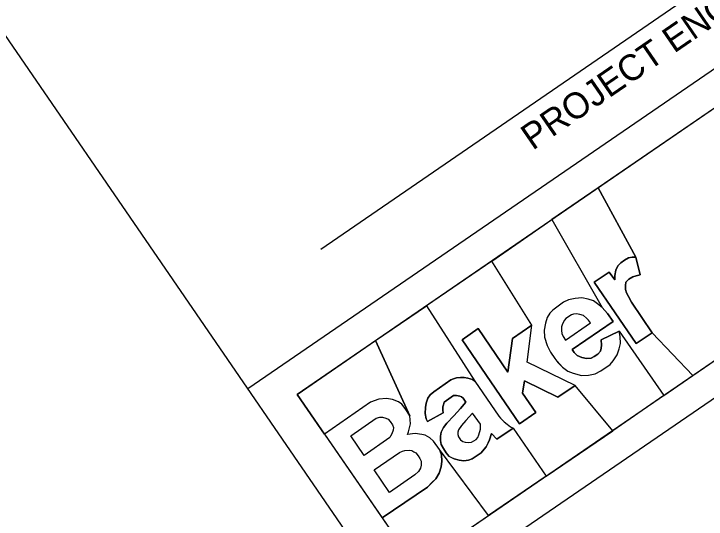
# Model space of a CAD drawing. Extents: x 2385901 to 2398444, y 552503 to 560579.
# Drawn here: x 2397033.1 to 2397262.8, y 560053.3 to 560221 of the extents above; entities that cross this region are included whole.
import ezdxf

# ---------------------------------------------------------------- set-up
doc = ezdxf.new("R2010")
doc.units = 0
doc.layers.add('Old_Level_8', color=7, linetype='Continuous')
doc.layers.add('Prop EOT', color=7, linetype='Continuous')

msp = doc.modelspace()

# ---------------------------------------------------------------- linework, layer by layer
at = {"layer": 'Old_Level_8'}
for p, q in [((2397154.02, 560033.5), (2396965.64, 560308.1)), ((2397407.68, 560300.28), (2397110.74, 560096.58)), ((2397172.79, 560030), (2397447.42, 560218.4)), ((2397230.65, 560135.28), (2397225.6, 560131.91)), ((2397232.47, 560132.66), (2397230.65, 560135.28)), ((2397225.6, 560131.91), (2397239.58, 560111.58)), ((2397244.91, 560115.17), (2397237.99, 560125.3)), ((2397205, 560117.69), (2397198.52, 560113.21)), ((2397187.11, 560116.56), (2397181.8, 560112.77)), ((2397197, 560102.1), (2397187.11, 560116.56)), ((2397239.58, 560111.58), (2397244.91, 560115.17)), ((2397181.8, 560112.77), (2397200.87, 560084.97)), ((2397198.52, 560113.21), (2397197, 560102.1)), ((2397213.54, 560093.74), (2397219.33, 560097.69)), ((2397206.24, 560088.65), (2397201.82, 560095.13)), ((2397151.46, 560092.08), (2397136.21, 560081.53)), ((2397154.25, 560093.12), (2397151.46, 560092.08)), ((2397156.75, 560093.37), (2397154.25, 560093.12)), ((2397158.73, 560092.99), (2397156.75, 560093.37)), ((2397160.67, 560092.2), (2397158.73, 560092.99)), ((2397161.85, 560091.41), (2397160.67, 560092.2)), ((2397164.45, 560087.54), (2397163.42, 560089.37)), ((2397164.71, 560084.87), (2397164.45, 560087.54)), ((2397200.87, 560084.97), (2397206.24, 560088.65)), ((2397144.94, 560080.97), (2397153.28, 560086.84)), ((2397164.03, 560082.25), (2397164.71, 560084.87)), ((2397136.21, 560081.53), (2397155.25, 560053.73)), ((2397144.92, 560080.96), (2397144.94, 560080.97)), ((2397149.3, 560074.44), (2397144.92, 560080.96)), ((2397157.82, 560080.35), (2397149.3, 560074.44)), ((2397163.69, 560081.34), (2397164.03, 560082.25)), ((2397166.21, 560081.7), (2397163.69, 560081.34)), ((2397168.51, 560081.4), (2397166.21, 560081.7)), ((2397169.54, 560081.17), (2397168.51, 560081.4)), ((2397171.15, 560080.23), (2397169.54, 560081.17)), ((2397172.38, 560079.19), (2397171.15, 560080.23)), ((2397174.31, 560076.43), (2397172.38, 560079.19)), ((2397175, 560074.61), (2397174.31, 560076.43)), ((2397152.62, 560069.65), (2397161.05, 560075.43)), ((2397175.07, 560072.56), (2397175, 560074.61)), ((2397174.86, 560070.62), (2397175.07, 560072.56)), ((2397157.71, 560062.14), (2397152.62, 560069.65)), ((2397174.19, 560068.58), (2397174.86, 560070.62)), ((2397166.14, 560068.01), (2397157.71, 560062.14)), ((2397171.81, 560065.47), (2397173.11, 560066.68)), ((2397173.11, 560066.68), (2397174.19, 560068.58)), ((2397170.3, 560063.94), (2397171.81, 560065.47)), ((2397155.25, 560053.73), (2397170.3, 560063.94))]:
    msp.add_line(p, q, dxfattribs=at)
for points in [[(2397275.68, 560196.62), (2397127.13, 560094.71), (2397166.2, 560037.75), (2397314.74, 560139.68)], [(2397227, 560163.25), (2397239.39, 560140.23), (2397240.84, 560134.42), (2397239.5, 560134.08), (2397238.44, 560133.76), (2397237.14, 560132.9), (2397236.15, 560131.93), (2397235.97, 560130.87), (2397235.98, 560129.54), (2397236.35, 560128.45), (2397236.97, 560127.16), (2397237.99, 560125.3), (2397244.91, 560115.17), (2397258.35, 560100.97), (2397314.74, 560139.68), (2397275.68, 560196.62)], [(2397211.62, 560152.7), (2397228.29, 560123.57), (2397230.08, 560121.56), (2397231.93, 560118.9), (2397218.3, 560109.58), (2397219.01, 560108.55), (2397219.97, 560107.58), (2397221.55, 560106.92), (2397223.13, 560106.61), (2397224.6, 560106.68), (2397225.65, 560107.23), (2397226.87, 560108.04), (2397227.72, 560109), (2397227.97, 560109.99), (2397228.1, 560111.04), (2397227.99, 560112.85), (2397233.86, 560115.71), (2397248.69, 560094.31), (2397258.35, 560100.97), (2397244.91, 560115.17), (2397239.58, 560111.58), (2397225.6, 560131.91), (2397230.65, 560135.28), (2397232.47, 560132.66), (2397232.49, 560134.13), (2397232.78, 560135.87), (2397233.44, 560137.4), (2397234.5, 560138.36), (2397235.68, 560139.23), (2397237, 560140.02), (2397238.18, 560140.22), (2397239.39, 560140.23), (2397227, 560163.25)], [(2397233.86, 560115.71), (2397248.69, 560094.31), (2397231.77, 560082.65), (2397219.33, 560097.69), (2397203.39, 560105.35), (2397205, 560117.69), (2397191.63, 560138.96), (2397211.62, 560152.7), (2397228.29, 560123.57), (2397226.73, 560124.74), (2397225.35, 560125.74), (2397223.65, 560126.26), (2397221.58, 560126.73), (2397219.32, 560126.55), (2397217.08, 560126.12), (2397215.44, 560125.29), (2397211.86, 560122.62), (2397210.87, 560121.6), (2397209.99, 560120.21), (2397209.53, 560118.38), (2397209.08, 560115.98), (2397209.2, 560113.73), (2397209.99, 560110.92), (2397211.12, 560108.76), (2397212.52, 560106.64), (2397215.08, 560103.71), (2397216.9, 560102.42), (2397218.65, 560101.7), (2397221.38, 560100.98), (2397223.78, 560101.09), (2397225.96, 560101.56), (2397227.87, 560102.55), (2397230.95, 560104.64), (2397231.9, 560105.87), (2397233.28, 560107.86), (2397233.92, 560109.76), (2397234.32, 560111.55), (2397234.25, 560113.86)], [(2397170, 560124.12), (2397186.07, 560099.12), (2397194.01, 560087.5), (2397194.6, 560086.81), (2397195.78, 560085.6), (2397196.73, 560084.81), (2397197.91, 560083.98), (2397198.74, 560083.5), (2397209.68, 560067.55), (2397231.77, 560082.65), (2397219.33, 560097.69), (2397213.54, 560093.74), (2397202.51, 560099.21), (2397201.82, 560095.13), (2397206.24, 560088.65), (2397200.87, 560084.97), (2397181.8, 560112.77), (2397187.11, 560116.56), (2397197, 560102.1), (2397198.52, 560113.21), (2397205, 560117.69), (2397191.63, 560138.96)], [(2397164.45, 560087.54), (2397153.12, 560112.54), (2397170, 560124.12), (2397186.07, 560099.12), (2397185.21, 560099.66), (2397183.7, 560100.11), (2397182.48, 560100.32), (2397181.32, 560100.31), (2397179.94, 560100.21), (2397178.93, 560099.89), (2397178.08, 560099.57), (2397172.41, 560095.53), (2397171.27, 560094.52), (2397170.48, 560093.46), (2397169.89, 560091.74), (2397169.64, 560090.32), (2397169.55, 560088.37), (2397169.86, 560086.6), (2397170.3, 560085.67), (2397175.56, 560088.52), (2397175.38, 560089.45), (2397175.43, 560090.62), (2397175.6, 560091.26), (2397175.87, 560092.14), (2397179, 560094.32), (2397179.97, 560094.35), (2397181.06, 560094.16), (2397181.58, 560093.91), (2397182.21, 560093.41), (2397183.08, 560092.11), (2397181.23, 560089.97), (2397179.02, 560087.59), (2397176.78, 560085.17), (2397175.67, 560083.74), (2397174.88, 560082.13), (2397174.62, 560080.81), (2397174.67, 560079.42), (2397174.86, 560078.09), (2397175.6, 560076.71), (2397176.5, 560075.35), (2397177.47, 560074.15), (2397179.14, 560073.29), (2397180.84, 560072.85), (2397182.4, 560072.7), (2397183.93, 560072.88), (2397185.1, 560073.33), (2397188.13, 560075.32), (2397188.63, 560075.84), (2397189.75, 560077.34), (2397190.45, 560078.66), (2397190.91, 560079.64), (2397191.56, 560081.69), (2397193.33, 560079.85), (2397198.74, 560083.5), (2397209.68, 560067.55), (2397190.62, 560054.47), (2397174.31, 560076.43), (2397172.38, 560079.19), (2397171.15, 560080.23), (2397169.54, 560081.17), (2397168.51, 560081.4), (2397166.21, 560081.7), (2397163.69, 560081.34), (2397164.03, 560082.25), (2397164.71, 560084.87)], [(2397216.08, 560112.69), (2397224.4, 560118.42), (2397223.74, 560119.31), (2397223.13, 560119.94), (2397222.11, 560120.87), (2397220.89, 560121.25), (2397219.72, 560121.38), (2397218.75, 560121.27), (2397218.06, 560121.09), (2397216.26, 560119.85), (2397215.75, 560119.36), (2397215.13, 560118.06), (2397214.79, 560117.12), (2397214.84, 560115.91), (2397214.95, 560114.85), (2397215.37, 560113.94)], [(2397164.45, 560087.54), (2397163.42, 560089.37), (2397162.58, 560090.42), (2397161.85, 560091.41), (2397160.67, 560092.2), (2397158.73, 560092.99), (2397156.75, 560093.37), (2397154.25, 560093.12), (2397151.46, 560092.08), (2397136.21, 560081.53), (2397127.13, 560094.71), (2397153.12, 560112.54)], [(2397144.94, 560080.97), (2397153.28, 560086.84), (2397154.5, 560087.15), (2397155.46, 560087.14), (2397156.53, 560086.82), (2397157.26, 560086.51), (2397157.97, 560085.66), (2397158.78, 560084.55), (2397159.04, 560083.71), (2397158.9, 560082.81), (2397158.55, 560081.63), (2397158.08, 560080.78), (2397157.82, 560080.35), (2397149.3, 560074.44)], [(2397185.3, 560088.49), (2397183.02, 560086.08), (2397181.66, 560084.42), (2397180.58, 560082.98), (2397180.41, 560082.17), (2397180.36, 560081.43), (2397180.67, 560080.56), (2397181.32, 560079.61), (2397182.11, 560079.05), (2397182.84, 560078.8), (2397183.91, 560078.72), (2397184.94, 560078.84), (2397186.46, 560079.76), (2397187.01, 560080.44), (2397187.33, 560081.29), (2397187.92, 560083.1), (2397187.96, 560084.14), (2397187.89, 560084.85)], [(2397152.62, 560069.65), (2397161.05, 560075.43), (2397162.05, 560075.88), (2397162.86, 560076.06), (2397164.3, 560076.17), (2397165.18, 560076.03), (2397165.82, 560075.65), (2397166.43, 560075.28), (2397167.24, 560074.35), (2397167.78, 560073.38), (2397168.21, 560072.54), (2397168.2, 560071.25), (2397167.98, 560070.17), (2397167.35, 560069.1), (2397166.14, 560068.01), (2397157.71, 560062.14)], [(2397174.31, 560076.43), (2397175, 560074.61), (2397175.07, 560072.56), (2397174.86, 560070.62), (2397174.19, 560068.58), (2397173.11, 560066.68), (2397170.3, 560063.94), (2397155.25, 560053.73), (2397166.2, 560037.75), (2397190.62, 560054.47)]]:
    msp.add_lwpolyline(points, close=True, dxfattribs=at)
for points in [[(2397237.99, 560125.3), (2397236.97, 560127.16), (2397236.35, 560128.45), (2397235.98, 560129.54), (2397235.97, 560130.87), (2397236.15, 560131.93), (2397237.14, 560132.9), (2397238.44, 560133.76), (2397239.5, 560134.08), (2397240.84, 560134.42), (2397239.39, 560140.23), (2397238.18, 560140.22), (2397237, 560140.02), (2397235.68, 560139.23), (2397234.5, 560138.36), (2397233.44, 560137.4), (2397232.78, 560135.87), (2397232.49, 560134.13), (2397232.47, 560132.66)], [(2397218.3, 560109.58), (2397231.93, 560118.9), (2397230.08, 560121.56), (2397228.29, 560123.57), (2397226.73, 560124.74), (2397225.35, 560125.74), (2397223.65, 560126.26), (2397221.58, 560126.73), (2397219.32, 560126.55), (2397217.08, 560126.12), (2397215.44, 560125.29), (2397211.86, 560122.62), (2397210.87, 560121.6), (2397209.99, 560120.21), (2397209.53, 560118.38), (2397209.08, 560115.98), (2397209.2, 560113.73), (2397209.99, 560110.92), (2397211.12, 560108.76), (2397212.52, 560106.64), (2397213.59, 560105.25), (2397215.08, 560103.71), (2397216.9, 560102.42), (2397218.65, 560101.7), (2397221.38, 560100.98), (2397223.78, 560101.09), (2397225.96, 560101.56), (2397227.87, 560102.55), (2397230.95, 560104.64), (2397231.9, 560105.87), (2397233.28, 560107.86), (2397233.92, 560109.76), (2397234.32, 560111.55), (2397234.25, 560113.86), (2397233.86, 560115.71), (2397227.99, 560112.85), (2397228.1, 560111.04), (2397227.97, 560109.99), (2397227.72, 560109), (2397226.87, 560108.04), (2397225.65, 560107.23), (2397224.6, 560106.68), (2397223.13, 560106.61), (2397221.55, 560106.92), (2397219.97, 560107.58), (2397219.01, 560108.55), (2397218.3, 560109.58)], [(2397216.08, 560112.69), (2397224.4, 560118.42), (2397223.74, 560119.31), (2397223.13, 560119.94), (2397222.11, 560120.87), (2397220.89, 560121.25), (2397219.72, 560121.38), (2397218.75, 560121.27), (2397218.06, 560121.09), (2397216.26, 560119.85), (2397215.75, 560119.36), (2397215.13, 560118.06), (2397214.79, 560117.12), (2397214.84, 560115.91), (2397214.95, 560114.85), (2397215.37, 560113.94), (2397216.08, 560112.69)], [(2397219.33, 560097.69), (2397203.39, 560105.35), (2397205, 560117.69)], [(2397175.56, 560088.52), (2397170.3, 560085.67), (2397169.86, 560086.6), (2397169.55, 560088.37), (2397169.64, 560090.32), (2397169.89, 560091.74), (2397170.48, 560093.46), (2397171.27, 560094.52), (2397172.41, 560095.53), (2397178.08, 560099.57), (2397178.93, 560099.89), (2397179.94, 560100.21), (2397181.32, 560100.31), (2397182.48, 560100.32), (2397183.7, 560100.11), (2397185.21, 560099.66), (2397186.07, 560099.12), (2397194.01, 560087.5), (2397194.6, 560086.81), (2397195.78, 560085.6), (2397196.73, 560084.81), (2397197.91, 560083.98), (2397198.74, 560083.5), (2397193.33, 560079.85), (2397191.56, 560081.69), (2397190.91, 560079.64), (2397190.45, 560078.66), (2397189.75, 560077.34), (2397188.63, 560075.84), (2397188.13, 560075.32), (2397185.1, 560073.33), (2397183.93, 560072.88), (2397182.4, 560072.7), (2397180.84, 560072.85), (2397179.14, 560073.29), (2397178.16, 560073.78), (2397177.47, 560074.15), (2397177.13, 560074.61), (2397176.5, 560075.35), (2397175.6, 560076.71), (2397174.86, 560078.09), (2397174.67, 560079.42), (2397174.62, 560080.81), (2397174.88, 560082.13), (2397175.67, 560083.74), (2397176.78, 560085.17), (2397179.02, 560087.59), (2397181.23, 560089.97), (2397183.08, 560092.11), (2397182.21, 560093.41), (2397181.58, 560093.91), (2397181.06, 560094.16), (2397179.97, 560094.35), (2397179, 560094.32), (2397175.87, 560092.14), (2397175.6, 560091.26), (2397175.43, 560090.62), (2397175.38, 560089.45), (2397175.56, 560088.52)], [(2397201.82, 560095.13), (2397202.51, 560099.21), (2397213.54, 560093.74)], [(2397163.42, 560089.37), (2397162.58, 560090.42), (2397161.85, 560091.41)], [(2397153.28, 560086.84), (2397154.5, 560087.15), (2397155.46, 560087.14), (2397156.53, 560086.82), (2397157.26, 560086.51), (2397157.97, 560085.66), (2397158.78, 560084.55), (2397159.04, 560083.71), (2397158.9, 560082.81), (2397158.55, 560081.63), (2397158.08, 560080.78), (2397157.82, 560080.35)], [(2397185.3, 560088.49), (2397183.02, 560086.08), (2397181.66, 560084.42), (2397180.58, 560082.98), (2397180.41, 560082.17), (2397180.36, 560081.43), (2397180.67, 560080.56), (2397181.32, 560079.61), (2397182.11, 560079.05), (2397182.84, 560078.8), (2397183.91, 560078.72), (2397184.94, 560078.84), (2397186.46, 560079.76), (2397187.01, 560080.44), (2397187.33, 560081.29), (2397187.92, 560083.1), (2397187.96, 560084.14), (2397187.89, 560084.85), (2397185.3, 560088.49)], [(2397161.05, 560075.43), (2397162.05, 560075.88), (2397162.86, 560076.06), (2397164.3, 560076.17), (2397165.18, 560076.03), (2397165.82, 560075.65), (2397166.43, 560075.28), (2397167.24, 560074.35), (2397167.78, 560073.38), (2397168.21, 560072.54), (2397168.2, 560071.25), (2397167.98, 560070.17), (2397167.35, 560069.1), (2397166.14, 560068.01)]]:
    msp.add_lwpolyline(points, dxfattribs=at)
at = {"layer": 'Prop EOT'}
msp.add_line((2397134.96, 560142.89), (2397355.19, 560294.17), dxfattribs=at)

# ---------------------------------------------------------------- texts
msp.add_text('PROJECT ENGINEER', height=8.6035, rotation=34.4849, dxfattribs=at).set_placement((2397205.22, 560175.5))

doc.saveas('drawing.dxf')
